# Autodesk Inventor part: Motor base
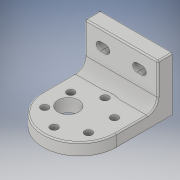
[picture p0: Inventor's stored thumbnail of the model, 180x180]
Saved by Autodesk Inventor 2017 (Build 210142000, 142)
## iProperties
Created: 2016-10
Part Number: Motor base
Material: Generic
Document SubType Name: Modeling
Designer: Stan
Density: 1 g/cm^3
Appearance: Default
Author: Stan
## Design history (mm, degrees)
sketch "Sketch1"
  geometry: L1 (-22.225, 0)-(-22.225, -34.925); L2 (-22.225, -34.925)-(22.225, -34.925); L3 (22.225, -34.925)-(22.225, 0); C1 r 6.35 at (6.858, 0); C2 r 2.286 at (0, 15.494); C3 r 2.286 at (0, -15.494); C4 r 2.286 at (13.322, 7.912); C5 r 2.286 at (13.322, -7.912); C6 r 2.286 at (-13.322, 7.912); C7 r 2.286 at (-13.322, -7.912); A1 r 22.225 centre (0, 0) between (22.225, 0) and (-22.225, 0); 1 further point
  constraints: 8 centre point, 6 end point, 2 point on circle, 1 coincident, 1 parallel
  dimensions: "d0" = 44.45 distance of L1.end L2.end; "d1" = 22.225 distance from line of L3 point (0, 0); "d3" = 12.7 diameter of C1; "d7" = 4.572 diameter of C2; "d8" = 4.572 diameter of C3; "d11" = 4.572 diameter of C4; "d12" = 4.572 diameter of C5; "d13" = 4.572 diameter of C6; "d14" = 4.572 diameter of C7; "d39" = 6.858 distance of point (0, 0) C1.centre
extrude "Extrusion1" new body sketch "Sketch1" distance "d17" = 7.9375; taper "d18" = 0 deg
sketch "Sketch2"
  geometry: L1 (-22.225, 34.925)-(-22.225, 0) reference; L2 (22.225, 0)-(22.225, 34.925) reference; L3 (-22.225, 34.925)-(22.225, 34.925); L4 (22.225, 34.925)-(22.225, 25.4); L5 (22.225, 25.4)-(-22.225, 25.4); L6 (-22.225, 25.4)-(-22.225, 34.925); 1 further point
  constraints: 8 end point, 2 parallel, 1 horizontal, 1 perpendicular, 1 point on line
  dimensions: "d19" = 9.525 distance between parallel lines of L5 L3
extrude "Extrusion2" join sketch "Sketch2" distance "d20" = 25.4; taper "d21" = 0 deg
fillet "Fillet1" dims "d22" = 6.35
sketch "Sketch3"
  geometry: C1 r 19.812 at (0, 0); 1 further point
  constraints: 1 centre point, 1 coincident
  dimensions: "d23" = 39.624 diameter of C1
extrude "Extrusion3" cut sketch "Sketch3" distance "d24" = 2.54; taper "d25" = 0 deg
sketch "Sketch4"
  geometry: L1 (0, -19.05)-(0, 0) reference; L2 (44.45, -19.05)-(44.45, 0) reference; L3 (0, 0)-(44.45, 0) reference; L4 (9.525, -6.985)-(12.7, -6.985); L5 (9.525, -12.065)-(12.7, -12.065); L6 (31.75, -12.065)-(34.925, -12.065); L7 (34.925, -6.985)-(31.75, -6.985); A1 r 2.54 centre (9.525, -9.525) between (9.525, -6.985) and (9.525, -12.065); A2 r 2.54 centre (34.925, -9.525) between (34.925, -12.065) and (34.925, -6.985); A3 r 2.54 centre (12.7, -9.525) between (12.7, -12.065) and (12.7, -6.985); A4 r 2.54 centre (31.75, -9.525) between (31.75, -6.985) and (31.75, -12.065); 1 further point
  constraints: 8 end point, 8 point on circle, 4 centre point, 4 point on line, 2 tangent
  dimensions: "d26" = 5.08 diameter of A1; "d27" = 5.08 diameter of A2; "d28" = 9.525 distance from line of L1 A1.centre; "d29" = 9.525 distance from line of L2 A2.centre; "d30" = 9.525 distance from line of A2.centre L3; "d31" = 9.525 distance from line of A1.centre L3; "d35" = 5.08 diameter of A3; "d36" = 5.08 diameter of A4; "d37" = 3.175 distance of A3.centre A1.centre; "d38" = 3.175 distance of A4.centre A2.centre
extrude "Extrusion4" cut sketch "Sketch4" distance "d32" = 9.525; taper "d33" = 0 deg
fillet "Fillet2" dims "d34" = 0.762
body "Solid1"
